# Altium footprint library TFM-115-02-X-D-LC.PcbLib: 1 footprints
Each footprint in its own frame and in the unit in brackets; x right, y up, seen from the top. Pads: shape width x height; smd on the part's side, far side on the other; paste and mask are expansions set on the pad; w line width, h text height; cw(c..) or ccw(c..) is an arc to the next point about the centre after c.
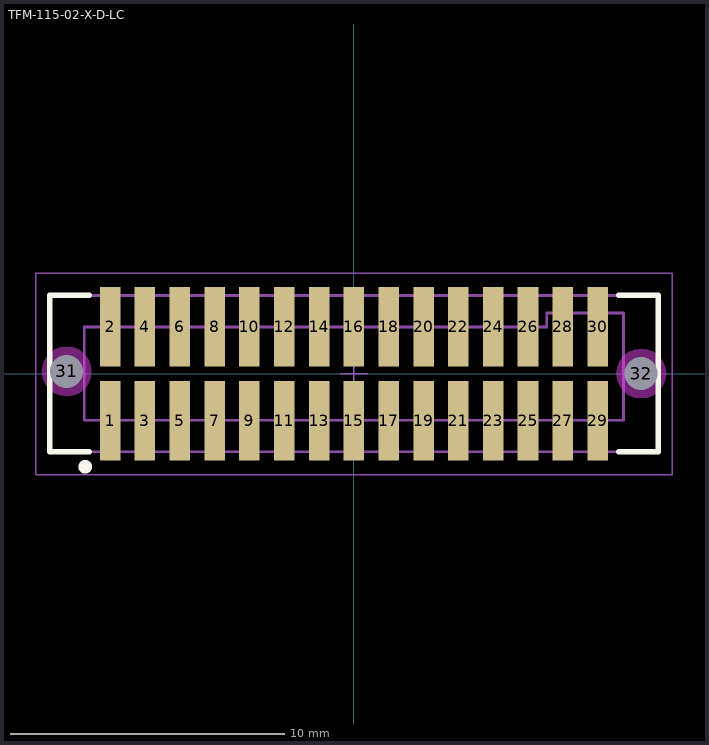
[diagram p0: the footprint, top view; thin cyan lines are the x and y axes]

## TFM-115-02-X-D-LC [mm] "1.27mm pitch, 30 pin, micro terminal strip; double row, w/locking clips, SMT"
height 9.27
pads (32):
  rect 0.75x2.9 smd mask+0: 1(-8.89,-1.714) 2(-8.89,1.714) 3(-7.62,-1.714) 4(-7.62,1.714) 5(-6.35,-1.714) 6(-6.35,1.714) 7(-5.08,-1.714) 8(-5.08,1.714) 9(-3.81,-1.714) 10(-3.81,1.714) 11(-2.54,-1.714) 12(-2.54,1.714) 13(-1.27,-1.714) 14(-1.27,1.714) 15(0,-1.714) 16(0,1.714) 17(1.27,-1.714) 18(1.27,1.714) 19(2.54,-1.714) 20(2.54,1.714) 21(3.81,-1.714) 22(3.81,1.714) 23(5.08,-1.714) 24(5.08,1.714) 25(6.35,-1.714) 26(6.35,1.714) 27(7.62,-1.714) 28(7.62,1.714) 29(8.89,-1.714) 30(8.89,1.714)
  round 1 hole 1.2 unplated mask+0: 31(-10.477,0.076) 32(10.477,0)
Top Overlay:
  circle w0.25: c-9.8,-3.4 r0.125
  lines w0.2: -9.65,-2.85 -11.1,-2.85 -11.1,2.85 -9.65,2.85 ; 9.65,-2.85 11.1,-2.85 11.1,2.85 9.65,2.85
Keep-Out Layer:
  pour cut-out: 11.385,0 11.355,0.235 11.264,0.454 11.12,0.642 10.932,0.786 10.713,0.877 10.478,0.908 10.243,0.877 10.024,0.786 9.836,0.642 9.692,0.454 9.601,0.235 9.57,0 9.601,-0.235 9.692,-0.454 9.836,-0.642 10.024,-0.786 10.243,-0.877 10.478,-0.908 10.713,-0.877 10.932,-0.786 11.12,-0.642 11.264,-0.454 11.355,-0.235
  pour cut-out: -9.57,0.076 -9.601,0.311 -9.692,0.53 -9.836,0.718 -10.024,0.862 -10.243,0.953 -10.478,0.984 -10.713,0.953 -10.932,0.862 -11.12,0.718 -11.264,0.53 -11.355,0.311 -11.385,0.076 -11.355,-0.159 -11.264,-0.378 -11.12,-0.566 -10.932,-0.71 -10.713,-0.801 -10.478,-0.831 -10.243,-0.801 -10.024,-0.71 -9.836,-0.566 -9.692,-0.378 -9.601,-0.159
Mechanical 12:
  lines w0.001: -11.1,-2.85 -11.1,2.85 11.1,2.85 11.1,-2.85 -11.1,-2.85 ; -9.83,-1.702 -9.83,1.702 7.036,1.702 7.036,2.21 9.83,2.21 9.83,-1.702 -9.83,-1.702
Mechanical 13:
  lines w0.1: -11.1,-2.85 -11.1,2.85 11.1,2.85 11.1,-2.85 -11.1,-2.85 ; -9.83,-1.702 -9.83,1.702 7.036,1.702 7.036,2.21 9.83,2.21 9.83,-1.702 -9.83,-1.702
  text ".Designator" at 0,-0.127 h1.52
Mechanical 15:
  lines w0.05: -0.5,0 0.5,0 ; 0,-0.5 0,0.5 ; -11.6,-3.683 -11.6,3.65 11.608,3.65 11.608,-3.683 -11.6,-3.683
